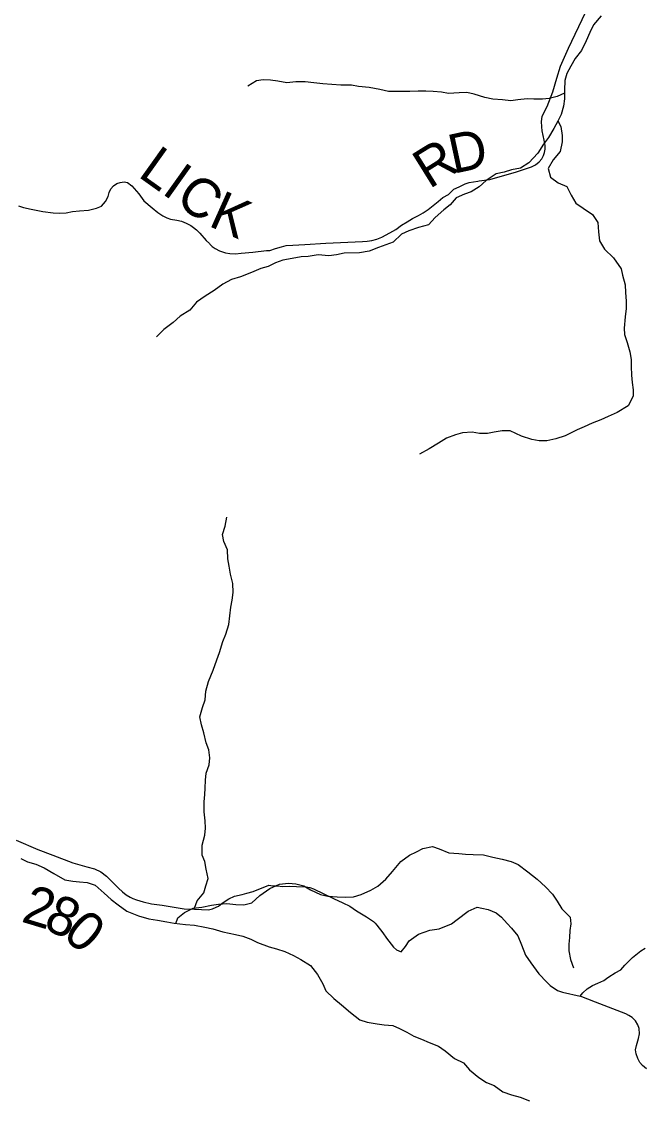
# Model space of a CAD drawing. Extents: x 0 to 44, y -23.8 to 22.
# Drawn here: x 3.029 to 3.933, y 14.979 to 16.572 of the extents above; entities that cross this region are included whole.
import ezdxf

# ---------------------------------------------------------------- set-up
doc = ezdxf.new("R2010")
doc.units = 0
for name, color, linetype in [('GM_X_County_Text', 7, 'Continuous'), ('GM_X_Minor_River', 7, 'Continuous'), ('GM_X_Township_Road', 7, 'Continuous'), ('GM_X_Township_Road_Text', 7, 'Continuous')]:
    doc.layers.add(name, color=color, linetype=linetype)

msp = doc.modelspace()

# ---------------------------------------------------------------- linework, layer by layer
at = {"layer": 'GM_X_Minor_River'}
for points in [[(3.8709, 16.5807), (3.8599, 16.5675), (3.8545, 16.5565), (3.8495, 16.5444), (3.8423, 16.5304), (3.8335, 16.5187), (3.827, 16.5074), (3.8213, 16.4968), (3.8185, 16.4869), (3.8177, 16.4729), (3.818, 16.4604), (3.8164, 16.4494), (3.8129, 16.4373), (3.808, 16.4275), (3.8022, 16.4169), (3.7946, 16.404), (3.7873, 16.3942), (3.7789, 16.3814), (3.766, 16.3674), (3.7539, 16.3595), (3.7406, 16.3569), (3.73, 16.3536), (3.7183, 16.351), (3.7042, 16.3416), (3.6936, 16.3322), (3.6822, 16.3251), (3.6727, 16.3217), (3.6602, 16.3165), (3.6518, 16.3063), (3.6423, 16.2987), (3.6298, 16.2878), (3.6202, 16.2773), (3.6055, 16.2732), (3.5914, 16.2683), (3.5808, 16.2635), (3.5687, 16.2518), (3.5474, 16.2443), (3.5338, 16.2387), (3.5198, 16.2365), (3.4975, 16.2359), (3.4865, 16.2333), (3.4751, 16.2322), (3.4596, 16.2335), (3.4453, 16.2313), (3.435, 16.2306), (3.4218, 16.2284), (3.4082, 16.2258), (3.3979, 16.2217), (3.3873, 16.2168), (3.3763, 16.2135), (3.363, 16.2079), (3.3468, 16.2015), (3.3339, 16.1978), (3.321, 16.1907), (3.3084, 16.1817), (3.2955, 16.1734), (3.283, 16.1648), (3.2731, 16.1531), (3.259, 16.1444), (3.2488, 16.1354), (3.2355, 16.1248), (3.2248, 16.1143)], [(3.8178, 16.4683), (3.8074, 16.4635), (3.7957, 16.4605), (3.7859, 16.4598), (3.7734, 16.4595), (3.7636, 16.4603), (3.7499, 16.4585), (3.7397, 16.4571), (3.7276, 16.4587), (3.7136, 16.4595), (3.7019, 16.4622), (3.6864, 16.4669), (3.6759, 16.4692), (3.6645, 16.4689), (3.649, 16.4679), (3.6388, 16.4698), (3.6271, 16.4706), (3.6161, 16.4711), (3.6052, 16.4712), (3.5931, 16.4709), (3.5621, 16.471), (3.5492, 16.4738), (3.5337, 16.4765), (3.5186, 16.4781), (3.5084, 16.4801), (3.4925, 16.4798), (3.4668, 16.4822), (3.4536, 16.4835), (3.4408, 16.4847), (3.4271, 16.4848), (3.4143, 16.4833), (3.4011, 16.4857), (3.3905, 16.4873), (3.3799, 16.4877), (3.3701, 16.4862), (3.3575, 16.4784)], [(3.8083, 16.4281), (3.8125, 16.4198), (3.8143, 16.4069), (3.8142, 16.3975), (3.8115, 16.3838), (3.8012, 16.3717), (3.7943, 16.3589), (3.7976, 16.3463), (3.8086, 16.3383), (3.8214, 16.3326), (3.8277, 16.32), (3.8345, 16.3086), (3.845, 16.3013), (3.8586, 16.2921), (3.8664, 16.2803), (3.8671, 16.2667), (3.8685, 16.2538), (3.876, 16.2416), (3.8888, 16.229), (3.9001, 16.2134), (3.9023, 16.2039), (3.906, 16.1898), (3.9067, 16.1788), (3.9073, 16.1663), (3.9073, 16.1557), (3.9061, 16.1432), (3.9044, 16.1272), (3.9051, 16.1178), (3.9089, 16.106), (3.9129, 16.0927), (3.9148, 16.0813), (3.9147, 16.0714), (3.915, 16.0589), (3.9161, 16.0479), (3.9175, 16.0376), (3.9178, 16.0282), (3.9102, 16.0142), (3.8946, 16.0044), (3.8813, 15.9984), (3.8707, 15.9939), (3.8582, 15.9887), (3.8465, 15.9835), (3.8362, 15.9794), (3.8188, 15.9704), (3.8051, 15.9663), (3.7919, 15.9633), (3.7809, 15.9634), (3.7703, 15.9653), (3.7552, 15.97), (3.7387, 15.9777), (3.7273, 15.9777), (3.7156, 15.9759), (3.7057, 15.9741), (3.6944, 15.9738), (3.6834, 15.9757), (3.6694, 15.9747), (3.6592, 15.9721), (3.6463, 15.9672), (3.6349, 15.9597), (3.6213, 15.9515), (3.6072, 15.944)], [(3.2798, 15.2843), (3.2837, 15.2947), (3.2936, 15.3064), (3.2963, 15.3166), (3.2998, 15.3272), (3.2972, 15.3409), (3.295, 15.3519), (3.2913, 15.3614), (3.291, 15.3758), (3.2952, 15.3902), (3.2961, 15.4004), (3.2954, 15.4111), (3.2939, 15.424), (3.294, 15.4388), (3.2949, 15.4494), (3.2953, 15.4588), (3.2961, 15.4702), (3.2969, 15.4805), (3.3012, 15.4926), (3.3024, 15.5028), (3.3009, 15.5142), (3.2968, 15.5245), (3.2935, 15.5389), (3.2902, 15.5507), (3.288, 15.5624), (3.2915, 15.5757), (3.2957, 15.587), (3.2965, 15.5996), (3.3004, 15.6136), (3.3073, 15.6302), (3.3123, 15.6453), (3.3162, 15.6559), (3.3212, 15.6718), (3.3254, 15.6824), (3.33, 15.6964), (3.3316, 15.709), (3.3328, 15.7215), (3.3348, 15.7317), (3.336, 15.7431), (3.3357, 15.756), (3.3324, 15.7696), (3.3305, 15.781), (3.3287, 15.7917), (3.328, 15.8049), (3.3225, 15.8171), (3.3206, 15.827), (3.3245, 15.8395), (3.3268, 15.8523)], [(3.2528, 15.2621), (3.2556, 15.2702), (3.2654, 15.2781), (3.2783, 15.2841), (3.2908, 15.2855), (3.3045, 15.2885), (3.3147, 15.2903), (3.3268, 15.291), (3.34, 15.2894), (3.3517, 15.2893), (3.3635, 15.2919), (3.3749, 15.3025), (3.3893, 15.313), (3.4037, 15.319), (3.4166, 15.3208), (3.4272, 15.3196), (3.4389, 15.3165), (3.4487, 15.3111), (3.4634, 15.3042), (3.4739, 15.3015), (3.4876, 15.3007), (3.4997, 15.3002), (3.511, 15.3005), (3.5224, 15.3042), (3.5364, 15.3102), (3.5466, 15.3162), (3.558, 15.3264), (3.568, 15.3377), (3.5801, 15.3521), (3.5927, 15.3611), (3.6025, 15.3663), (3.612, 15.3708), (3.626, 15.3738), (3.6358, 15.3703), (3.6498, 15.3649), (3.6642, 15.3637), (3.674, 15.3629), (3.6853, 15.3624), (3.7001, 15.362), (3.7137, 15.3585), (3.7273, 15.3557), (3.7401, 15.3522), (3.7507, 15.3476), (3.7646, 15.3373), (3.7781, 15.3266), (3.7902, 15.3155), (3.8003, 15.3045), (3.8074, 15.2946), (3.8138, 15.2835), (3.8262, 15.2713), (3.8269, 15.2614), (3.8257, 15.2516), (3.8249, 15.2417), (3.8241, 15.2322), (3.824, 15.2224), (3.8266, 15.2099), (3.8307, 15.1977)], [(3.0277, 15.3565), (3.0375, 15.3516), (3.0496, 15.3484), (3.0613, 15.3427), (3.0756, 15.3346), (3.0918, 15.3254), (3.1031, 15.3235), (3.1129, 15.3227), (3.1239, 15.3218), (3.1356, 15.3176), (3.1488, 15.3061), (3.1589, 15.297), (3.1691, 15.2889), (3.1819, 15.2798), (3.1985, 15.2732), (3.2136, 15.2689), (3.2264, 15.267), (3.24, 15.2642), (3.2506, 15.2623), (3.2668, 15.2607), (3.2801, 15.2594), (3.2952, 15.2567), (3.3065, 15.2543), (3.3212, 15.2497), (3.3394, 15.2458), (3.3503, 15.2435), (3.362, 15.2392), (3.3718, 15.2346), (3.3884, 15.2281), (3.3994, 15.225), (3.4114, 15.2211), (3.4239, 15.2157), (3.4348, 15.2096), (3.4484, 15.2011), (3.4589, 15.1878), (3.4667, 15.1741), (3.4708, 15.1642), (3.4825, 15.1532), (3.4938, 15.1436), (3.5066, 15.1329), (3.5201, 15.1218), (3.5311, 15.1187), (3.5454, 15.1164), (3.5556, 15.1148), (3.5681, 15.1136), (3.5779, 15.1093), (3.5888, 15.104), (3.5986, 15.0982), (3.6099, 15.094), (3.6213, 15.089), (3.6345, 15.084), (3.6442, 15.0771), (3.6578, 15.066), (3.671, 15.0595), (3.6796, 15.0496), (3.6935, 15.0381), (3.7045, 15.0312), (3.7158, 15.0266), (3.7282, 15.0174), (3.7407, 15.0132), (3.7535, 15.0097), (3.7671, 15.0043)]]:
    msp.add_lwpolyline(points, dxfattribs=at)
at = {"layer": 'GM_X_Township_Road'}
for points in [[(3.6936, 16.3409), (3.7091, 16.3432), (3.7279, 16.3484), (3.7466, 16.3534), (3.7598, 16.3578), (3.7698, 16.3612), (3.7759, 16.3641), (3.7811, 16.3685), (3.7847, 16.3729), (3.7872, 16.3777), (3.7889, 16.3823), (3.7899, 16.3869), (3.7897, 16.3922), (3.7885, 16.4003), (3.7853, 16.4139), (3.7849, 16.4194), (3.7843, 16.427), (3.7855, 16.4343), (3.7882, 16.441), (3.7924, 16.4491), (3.8008, 16.4705), (3.8069, 16.4904), (3.8119, 16.5075), (3.8238, 16.5339), (3.8485, 16.5854)], [(3.3023, 16.2491), (3.3056, 16.2458), (3.31, 16.2429), (3.3165, 16.2393), (3.3249, 16.2366), (3.3312, 16.2356), (3.3395, 16.2351), (3.3477, 16.2358), (3.3649, 16.2376), (3.3846, 16.2397), (3.3894, 16.2397), (3.3977, 16.2427), (3.4065, 16.2452), (3.4132, 16.2469), (3.4229, 16.2477), (3.4405, 16.2485), (3.471, 16.2506), (3.5242, 16.2531), (3.5311, 16.2533), (3.5378, 16.2542), (3.5449, 16.2563), (3.5521, 16.259), (3.564, 16.2653), (3.5728, 16.2705), (3.581, 16.2766), (3.5889, 16.2816), (3.5967, 16.2863), (3.6055, 16.2908), (3.6126, 16.2946), (3.6195, 16.2994), (3.627, 16.3053), (3.6341, 16.3109), (3.641, 16.3166), (3.6492, 16.321), (3.6571, 16.3288), (3.6647, 16.3325), (3.6733, 16.3365), (3.6794, 16.3386), (3.6854, 16.3394), (3.6917, 16.3407), (3.6936, 16.3409)], [(3.0242, 16.3046), (3.0315, 16.3023), (3.0424, 16.2998), (3.0598, 16.2963), (3.0745, 16.2946), (3.0843, 16.2942), (3.0933, 16.2946), (3.1027, 16.2963), (3.1128, 16.2975), (3.1258, 16.2984), (3.1375, 16.3011), (3.145, 16.3042), (3.1505, 16.3111), (3.1545, 16.3181), (3.1559, 16.3241), (3.1584, 16.3296), (3.1624, 16.334), (3.1672, 16.3373), (3.1722, 16.3388), (3.1777, 16.3394), (3.1825, 16.3386), (3.189, 16.3337), (3.1993, 16.322), (3.2062, 16.3122), (3.2183, 16.3017), (3.2267, 16.2948), (3.2342, 16.2902), (3.2397, 16.2873), (3.2453, 16.2854), (3.2545, 16.2837), (3.2612, 16.2822), (3.2681, 16.2795), (3.2748, 16.276), (3.2788, 16.273), (3.283, 16.2697), (3.2878, 16.2649), (3.2968, 16.2542), (3.3016, 16.2498), (3.3023, 16.2491)], [(3.0208, 15.3832), (3.0521, 15.3696), (3.0742, 15.3613), (3.1031, 15.35), (3.1233, 15.3444), (3.1346, 15.3413), (3.1441, 15.3371), (3.152, 15.3306), (3.1576, 15.3252), (3.1643, 15.3185), (3.1696, 15.3134), (3.1756, 15.308), (3.1809, 15.3037), (3.1864, 15.3003), (3.1902, 15.2985), (3.1957, 15.2965), (3.2054, 15.2934), (3.2177, 15.2904), (3.233, 15.2886), (3.2648, 15.2835), (3.2799, 15.2827), (3.3002, 15.2817), (3.306, 15.2833), (3.3115, 15.2855), (3.3151, 15.2874), (3.3198, 15.2912), (3.3244, 15.2942), (3.3301, 15.2979), (3.3382, 15.3015), (3.3493, 15.3043), (3.3559, 15.306), (3.3652, 15.3086), (3.3881, 15.3175), (3.3937, 15.3169), (3.4006, 15.3165), (3.4077, 15.3159), (3.4178, 15.3161), (3.4283, 15.3159), (3.4423, 15.3154), (3.4475, 15.3144), (3.4532, 15.3124), (3.4819, 15.2985), (3.4958, 15.2918), (3.5059, 15.2874), (3.5156, 15.2803), (3.5302, 15.2718), (3.5403, 15.2647), (3.5424, 15.2625)], [(3.5424, 15.2625), (3.5452, 15.2595), (3.5538, 15.2483), (3.5593, 15.2408), (3.5692, 15.2275), (3.5735, 15.2235), (3.5805, 15.2206), (3.5868, 15.2287), (3.5922, 15.2366), (3.6054, 15.2467), (3.6221, 15.2524), (3.6357, 15.2544), (3.6535, 15.2613), (3.662, 15.2679), (3.6778, 15.2799), (3.6907, 15.2857), (3.6978, 15.2845), (3.7069, 15.2823), (3.7184, 15.2777), (3.7261, 15.271), (3.7344, 15.2619), (3.7406, 15.255), (3.7501, 15.2443), (3.7554, 15.2308), (3.7612, 15.216), (3.7689, 15.2047), (3.7804, 15.1889), (3.7922, 15.1766), (3.797, 15.1719), (3.8077, 15.1647), (3.8148, 15.1624), (3.8407, 15.1564)], [(3.8407, 15.1564), (3.8447, 15.1614), (3.851, 15.1671), (3.8585, 15.1717), (3.8664, 15.1752), (3.875, 15.1792), (3.8789, 15.182), (3.8821, 15.1843), (3.8916, 15.1901), (3.8995, 15.1948), (3.9054, 15.2016), (3.9167, 15.2126), (3.9288, 15.2221), (3.9353, 15.2263)], [(3.9371, 15.0506), (3.9314, 15.0555), (3.9272, 15.0599), (3.9242, 15.0657), (3.9219, 15.0725), (3.9211, 15.0783), (3.9223, 15.0846), (3.9256, 15.0949), (3.927, 15.1018), (3.9264, 15.1095), (3.9246, 15.1149), (3.9209, 15.1204), (3.9161, 15.1256), (3.9112, 15.1283), (3.9068, 15.1309), (3.8627, 15.1479), (3.8407, 15.1564)]]:
    msp.add_lwpolyline(points, dxfattribs=at)

# ---------------------------------------------------------------- texts
at = {"layer": 'GM_X_County_Text'}
msp.add_text('SCIOTO COUNTY', height=0.189394, rotation=23.8999, dxfattribs=at).set_placement((2.9443, 14.3021))
at = {"layer": 'GM_X_Township_Road_Text'}
for s, rotation, p in [('D', 12.1894, (3.6562, 16.3511)), ('L', 324.5136, (3.1963, 16.3483)), ('R', 31.9123, (3.6213, 16.3284)), ('I', 324.4932, (3.2309, 16.3237)), ('C', 323.963, (3.2498, 16.3102)), ('K', 335.8868, (3.2987, 16.2763)), ('2', 343.2389, (3.0267, 15.2651)), ('8', 335.1387, (3.0582, 15.2558)), ('0', 319.3369, (3.0865, 15.2433))]:
    msp.add_text(s, height=0.0568, rotation=rotation, dxfattribs=at).set_placement(p)

doc.saveas('drawing.dxf')
